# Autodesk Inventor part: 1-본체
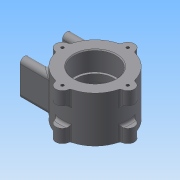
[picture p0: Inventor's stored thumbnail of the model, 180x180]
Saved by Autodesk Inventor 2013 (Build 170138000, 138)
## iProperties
Created: 2015-03
Part Number: 1-본체
Material: 일반
Document SubType Name: Modeling
Designer: ST3
Density: 1 g/cm^3
Author: ST3
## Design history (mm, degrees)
sketch "스케치1"
  geometry: C1 r 37 at (0, 0); 1 further point
  constraints: 1 centre point, 1 coincident
  dimensions: "d0" = 74 diameter of C1
extrude "돌출1" new body sketch "스케치1" distance "d2" = 52; taper "d3" = 0 deg
sketch "스케치2"
  geometry: C1 r 37 at (0, 0) reference; C2 r 23.5 at (0, 0)
  constraints: 1 centre point, 1 coincident
  dimensions: "d4" = 47 diameter of C2
extrude "돌출2" cut sketch "스케치2" distance "d6" = 22; taper "d7" = 0 deg
sketch "스케치3"
  geometry: C1 r 37 at (0, 0) reference; C2 r 23.5 at (0, 0)
  constraints: 1 centre point, 1 coincident
  dimensions: "d8" = 47 diameter of C2
extrude "돌출3" cut sketch "스케치3" distance "d11" = 22; taper "d12" = 0 deg
sketch "스케치4"
  geometry: C1 r 23.5 at (0, 0) reference; C2 r 21 at (0, 0)
  constraints: 1 centre point, 1 coincident
  dimensions: "d13" = 42 diameter of C2
extrude "돌출4" cut sketch "스케치4" stored distance "d15" = 22; taper "d16" = 0 deg
node "작업 평면2"
sketch "스케치6"
  geometry: L1 (-29, 11)-(-29, 41); L2 (-19, 41)-(-19, 11); L3 (19, 11)-(19, 41); L4 (29, 41)-(29, 11); L5 (-37, 0)-(37, 0) reference; L6 (37, 52)-(-37, 52) reference; L7 (0, 0)-(0, 52); L8 (-37, 0)-(-37, 52) reference; L9 (37, 0)-(37, 52) reference; L10 (-37, 26)-(37, 26); A1 r 5 centre (-24, 41) between (-19, 41) and (-29, 41); A2 r 5 centre (-24, 11) between (-29, 11) and (-19, 11); A3 r 5 centre (24, 41) between (29, 41) and (19, 41); A4 r 5 centre (24, 11) between (19, 11) and (29, 11)
  constraints: 12 end point, 8 point on circle, 8 tangent, 4 centre point, 3 midpoint, 3 parallel, 1 vertical
  dimensions: "d18" = 10 distance between parallel lines of L4 L3; "d20" = 10 distance between parallel lines of L2 L1; "d21" = 24 distance from line of L7 A1.centre; "d22" = 24 distance from line of L7 A3.centre; "d23" = 40 dimension on A1 A2; "d24" = 40 dimension on A3 A4; "d25" = 20 dimension on A2 L10; "d26" = 20 dimension on A4 L10
extrude "돌출5" join sketch "스케치6" stored distance "d27" = 22; taper "d28" = 0 deg
sketch "스케치7"
  geometry: C1 r 2.5 at (11, 24); C2 r 2.5 at (41, 24); A1 r 5 centre (41, 24) between (41, 19) and (41, 29) reference; A2 r 5 centre (11, 24) between (11, 29) and (11, 19) reference; 1 further point
  constraints: 2 centre point, 2 coincident
  dimensions: "d29" = 5 diameter of C2; "d32" = 5 diameter of C1
hole "구멍1" sketch "스케치7" at (11, 24), (41, 24) diameter "d33" = 4.134; stored, may be unused: countersink angle "d37" = 90 deg, drill point angle "d39" = 118 deg; dims "d34" = 6, "d35" = 4, "d36" = 2, "d38" = 8
sketch "스케치8"
  geometry: A1 r 5 centre (41, -24) between (41, -29) and (41, -19) reference; A2 r 5 centre (11, -24) between (11, -19) and (11, -29) reference; 1 further point
hole "구멍2" sketch "스케치8" at (11, -24), (41, -24) diameter "d40" = 4.134; stored, may be unused: countersink angle "d44" = 90 deg, drill point angle "d46" = 118 deg; dims "d41" = 6, "d42" = 4, "d43" = 2, "d45" = 8
sketch "스케치9"
  geometry: L1 (-37, 0)-(37, 0); L2 (0, -37)-(0, 37); C1 r 23.5 at (0, 0) reference; A1 r 37 centre (0, 0) between (-37, 0) and (37, 0) reference; A2 r 7.5 centre (-37, 0) between (-36.24, 7.461) and (-36.24, -7.461)
  constraints: 8 point on circle, 4 end point, 1 centre point, 1 coincident, 1 horizontal, 1 perpendicular
  dimensions: "d47" = 0 distance from line of C1.centre L1; "d48" = 0 distance from line of C1.centre L2; "d49" = 15 diameter of A2
extrude "돌출6" join sketch "스케치9" distance "d50" = 15; taper "d51" = 0 deg
sketch "스케치10"
  geometry: L1 (0, 0)-(37, 0); A1 r 37 centre (0, 0) between (37, 0) and (36.24, -7.461) reference; A2 r 7.5 centre (37, 0) between (36.24, -7.461) and (36.24, 7.461)
  constraints: 5 point on circle, 2 end point, 1 centre point, 1 coincident, 1 horizontal
  dimensions: "d55" = 15 diameter of A2
extrude "돌출7" join sketch "스케치10" distance "d57" = 15; taper "d58" = 0 deg
sketch "스케치11"
  geometry: A1 r 7.5 centre (0, 37) between (7.461, 36.24) and (-7.461, 36.24) reference; A2 r 7.5 centre (-37, 0) between (-36.24, 7.461) and (-36.24, -7.461) reference; A3 r 7.5 centre (0, -37) between (-7.461, -36.24) and (7.461, -36.24) reference; A4 r 7.5 centre (37, 0) between (36.24, -7.461) and (36.24, 7.461) reference
hole "구멍3" sketch "스케치11" at (37, 0), (0, 37), (0, -37), (-37, 0) diameter "d62" = 3.242; stored, may be unused: countersink angle "d66" = 90 deg, drill point angle "d68" = 118 deg; dims "d63" = 8, "d64" = 4, "d65" = 2, "d67" = 11
sketch "스케치12"
  geometry: A1 r 7.5 centre (0, -37) between (-7.461, -36.24) and (7.461, -36.24) reference; A2 r 7.5 centre (37, 0) between (36.24, -7.461) and (36.24, 7.461) reference; A3 r 7.5 centre (0, 37) between (7.461, 36.24) and (-7.461, 36.24) reference; A4 r 7.5 centre (-37, 0) between (-36.24, 7.461) and (-36.24, -7.461) reference
hole "구멍4" sketch "스케치12" at (-37, 0), (0, -37), (37, 0), (0, 37) diameter "d69" = 3.242; stored, may be unused: countersink angle "d73" = 90 deg, drill point angle "d75" = 118 deg; dims "d70" = 8, "d71" = 4, "d72" = 2, "d74" = 11
fillet "모깎기1" dims "d76" = 3
fillet "모깎기2" dims "d80" = 3
chamfer "모따기1" distance "d84" = 1; stored, may be unused: second distance "d85" = 2, angle "d86" = 45 deg
chamfer "모따기2" distance "d87" = 1; stored, may be unused: second distance "d88" = 2, angle "d89" = 45 deg
fillet "모깎기3" dims "d90" = 3
node "솔리드1"
pattern_circular "원형 패턴1" dims angle "d53" = 360 deg
pattern_circular "원형 패턴2" dims angle "d60" = 360 deg
pattern_circular "원형 패턴3" dims angle "d78" = 360 deg
pattern_circular "원형 패턴4" dims angle "d82" = 360 deg
other parameters: "d17" = -56
